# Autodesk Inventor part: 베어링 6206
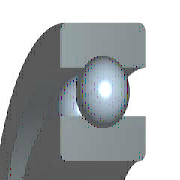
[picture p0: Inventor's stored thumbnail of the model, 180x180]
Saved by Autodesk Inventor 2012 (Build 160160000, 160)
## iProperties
Created: 2009-02
Part Number: 베어링 6206
Material: Steel, Mild
Description: 깊은 그루브 볼 베어링
Document SubType Name: Modeling
Standard: KS B 2023
Designer: KYOUNG IL JANG
Standards Organization: KS
Language: ko-KR
Size Designation: 6206 - 30 x 62 x 16
Categories: <MemberInstance><Categories><Category DisplayName="샤프트 부품" InternalName="7f7aeb1f-a693-4053-b835-cee3144e0d98" Mnemonic="SHFT"><Category DisplayName="베어링" Inter
Density: 1 g/cm^3
Company: 한국ATC센터
IsCustomPart: 0
Author: KYOUNG IL JANG
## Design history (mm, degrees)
revolve "본체" stored, may be unused: angle "d6" = 90 deg
revolve "볼" stored, may be unused: angle "d7" = 90 deg
pattern_circular "IDS_ARRAYBALL[SIMPL:T]" dims angle "d3" = 360 deg
body "Solid1"
sketch "스케치" dims "d0" = 8.32 (= -0.26 x WD + 0.26 x BD)
  geometry: L1 (3.84, 23)-(12.16, 23); L2 (8, 23)-(8, 18.84); L3 (8, 23)-(8, 27.16); L4 (4.909, 20.216)-(0, 20.216); L5 (0, 15)-(16, 15); L6 (4.909, 25.784)-(0, 25.784); L7 (0, 31)-(16, 31); L8 (16, 15)-(16, 20.216); L9 (11.091, 20.216)-(16, 20.216); L10 (11.091, 25.784)-(16, 25.784); L11 (16, 31)-(16, 25.784); L12 (-1.4, 0)-(8.4, 0) reference; L13 (0, -0.3)-(0, 5.3) reference
  constraints: 22 end point, 4 point on line, 2 collinear, 2 perpendicular, 2 symmetric about line, 1 midpoint, 1 parallel, 14 other
  dimensions: "d9" = 30 diameter of L5 L12 (= WD); "d11" = 62 diameter of L7 L12 (= BD); "d12" = 16 distance between parallel lines of L8 L13 (= KB); "d13" = 40.432 diameter of L9 L12 (= 0.326 x BD + 0.674 x WD)
fillet "모깎기1" dims "d1" = 1 (= KRS)
other parameters: "WD" = 30 [user parameter; used in 5 equation terms], "BD" = 62 [user parameter; used in 5 equation terms], "KB" = 16 [user parameter; used in 1 equation term], "KRS" = 1 [user parameter; used in 1 equation term], "d4" = 0, "d5" = 0, "d8" = 0, "d14" = 0, "d15" = 0, "BBA" = 0 [user parameter], "BC0" = 1.12e+07 [user parameter], "BC" = 1.95e+07 [user parameter], "BR" = 31 (= 0.5 x BD) [user parameter], "WR" = 15 (= 0.5 x WD) [user parameter]
